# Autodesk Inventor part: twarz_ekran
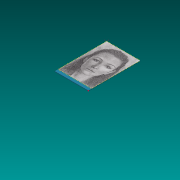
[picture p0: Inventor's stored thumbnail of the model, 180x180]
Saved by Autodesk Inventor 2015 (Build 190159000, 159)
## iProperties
Created: 2016-02
Part Number: twarz_ekran
Material: Generic
Document SubType Name: Modeling
Designer: Rafał
Density: 1 g/cm^3
Appearance: Turquoise
Author: Rafał
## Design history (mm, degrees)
sketch "Sketch1"
  geometry: L1 (0, 0)-(-107, 0); L2 (-107, 0)-(-107, 165); L3 (-107, 165)-(0, 165); L4 (0, 165)-(0, 0)
  constraints: 8 end point, 2 parallel, 1 horizontal, 1 perpendicular
  dimensions: "d0" = 107 distance of L2.end L3.end; "d1" = 165 distance of L1.end L2.end
extrude "Extrusion1" new body sketch "Sketch1" distance "d2" = 2; taper "d3" = 0 deg
sketch "Sketch2"
  geometry: L1 (-107, 165)-(-0.095, 165); L2 (-0.095, 165)-(-0.095, 10.066); L3 (-0.095, 10.066)-(-107, 10.066); L4 (-107, 10.066)-(-107, 165); 1 further point; 1 other entity
  constraints: 2 other
  node "Image2"
body "Solid1"
